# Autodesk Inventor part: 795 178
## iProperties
Created: 2009-08
Part Number: 795 178
Material: Kst - PE/UHMW - Schwarz
Document SubType Name: Modellieren
Designer: TMT
Manufacturer: Standard
Standards Organization: Custom
Density: 0.94 g/cm^3
Description: Grossbehälter (285 l) aus PE
Vendor: Kaiser+Kraft
Author: TMT
Comments: Kaiser+Kraft
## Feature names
1. Extrusion2
2. Extrusion3
3. Extrusion4
4. Extrusion5
5. Spiegeln1 [Mirror]
6. Spiegeln2 [Mirror]
7. Extrusion6
8. Spiegeln3 [Mirror]
9. Spiegeln4 [Mirror]
10. Extrusion7
11. Spiegeln5 [Mirror]
12. Spiegeln6 [Mirror]
13. Extrusion8
